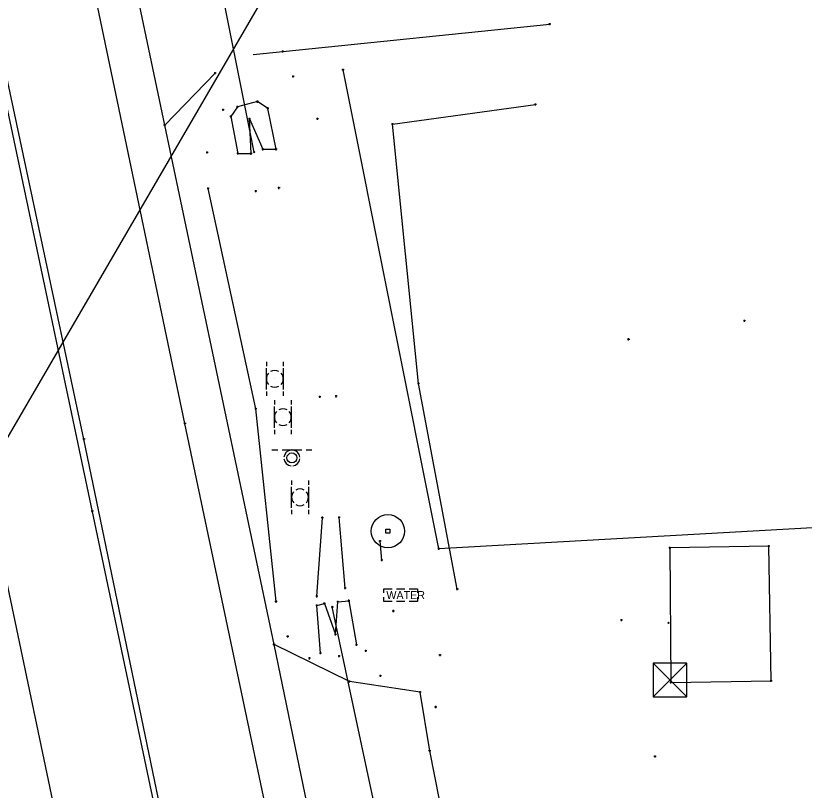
# Model space of a CAD drawing. Extents: x 1954856 to 2011933, y 399149 to 426294.
# Drawn here: x 2005465.1 to 2005558.7, y 405686.9 to 405778.8 of the extents above; entities that cross this region are included whole.
import ezdxf

# ---------------------------------------------------------------- set-up
doc = ezdxf.new("R2010")
doc.units = 0
for name, color, linetype in [('BankMent_ep', 7, 'Continuous'), ('BaselineSurvey', 7, 'Continuous'), ('Building_ep', 7, 'Continuous'), ('DelineatorPost_ep', 7, 'Continuous'), ('Driveway_ep', 7, 'Continuous'), ('ElecAer_ep', 7, 'Continuous'), ('EndTreatMES_ep', 7, 'Continuous'), ('FFElev_ep', 7, 'Continuous'), ('FlowLineInvert_ep', 7, 'Continuous'), ('MeterWater_ep', 7, 'Continuous'), ('MonumentPIP_ep', 7, 'Continuous'), ('MonumentPST_ep', 7, 'Continuous'), ('PavtAsphalt_ep', 7, 'Continuous'), ('PavtAsphaltCrown_ep', 7, 'Continuous'), ('PipeCulvert_ep', 7, 'Continuous'), ('PointLocator_ep', 7, 'Continuous'), ('ShldrPaved_ep', 7, 'Continuous'), ('SignSingle_ep', 7, 'Continuous'), ('TreeLineWoods_ep', 7, 'Continuous')]:
    doc.layers.add(name, color=color, linetype=linetype)

msp = doc.modelspace()

# ---------------------------------------------------------------- linework, layer by layer
at = {"layer": 'BankMent_ep'}
for p, q in [((2005509.866, 405765.963), (2005526.829, 405768.288)), ((2005512.931, 405735.184), (2005509.866, 405765.963)), ((2005493.618, 405732.173), (2005487.978, 405758.332)), ((2005517.542, 405710.799), (2005512.931, 405735.184)), ((2005496.025, 405709.31), (2005493.618, 405732.173)), ((2005500.874, 405709.942), (2005501.526, 405719.269)), ((2005504.222, 405710.912), (2005503.519, 405719.305)), ((2005508.586, 405714.238), (2005508.368, 405716.469))]:
    msp.add_line(p, q, dxfattribs=at)
at = {"layer": 'BaselineSurvey'}
msp.add_line((2006223.925, 402174.382), (2005094.479, 407516.047), dxfattribs=at)
msp.add_line((2006223.925, 402174.382), (2005094.479, 407516.047), dxfattribs=at)
at = {"layer": 'Building_ep'}
msp.add_lwpolyline([(2005542.763, 405715.684), (2005542.9, 405699.706), (2005554.797, 405699.906), (2005554.528, 405715.904)], close=True, dxfattribs=at)
at = {"layer": 'DelineatorPost_ep'}
for p, q in [((2005494.879, 405737.743), (2005494.879, 405737.243)), ((2005496.879, 405737.743), (2005496.879, 405737.243)), ((2005494.879, 405734.493), (2005494.879, 405736.993)), ((2005496.879, 405736.993), (2005496.879, 405734.493)), ((2005495.879, 405735.743), (2005495.879, 405735.743)), ((2005494.879, 405734.243), (2005494.879, 405733.743)), ((2005496.879, 405734.243), (2005496.879, 405733.743)), ((2005495.842, 405733.196), (2005495.842, 405732.696)), ((2005497.842, 405733.196), (2005497.842, 405732.696)), ((2005495.842, 405729.946), (2005495.842, 405732.446)), ((2005497.842, 405732.446), (2005497.842, 405729.946)), ((2005496.842, 405731.196), (2005496.842, 405731.196)), ((2005495.842, 405729.696), (2005495.842, 405729.196)), ((2005497.842, 405729.696), (2005497.842, 405729.196)), ((2005497.874, 405723.689), (2005497.874, 405723.189)), ((2005499.874, 405723.689), (2005499.874, 405723.189)), ((2005497.874, 405720.439), (2005497.874, 405722.939)), ((2005499.874, 405722.939), (2005499.874, 405720.439)), ((2005498.874, 405721.689), (2005498.874, 405721.689)), ((2005497.874, 405720.189), (2005497.874, 405719.689)), ((2005499.874, 405720.189), (2005499.874, 405719.689))]:
    msp.add_line(p, q, dxfattribs=at)
for centre, start, end in [((2005495.879, 405735.743), 60, 120), ((2005495.879, 405735.743), 138.59038, 221.40962), ((2005495.879, 405735.743), 318.59038, 41.40962), ((2005495.879, 405735.743), 240, 300), ((2005496.842, 405731.196), 60, 120), ((2005496.842, 405731.196), 138.59038, 221.40962), ((2005496.842, 405731.196), 318.59038, 41.40962), ((2005496.842, 405731.196), 240, 300), ((2005498.874, 405721.689), 60, 120), ((2005498.874, 405721.689), 138.59038, 221.40962), ((2005498.874, 405721.689), 318.59038, 41.40962), ((2005498.874, 405721.689), 240, 300)]:
    msp.add_arc(centre, 1, start, end, dxfattribs=at)
at = {"layer": 'Driveway_ep'}
for p, q in [((2005496.847, 405774.568), (2005528.511, 405777.824)), ((2005493.321, 405774.205), (2005496.847, 405774.568)), ((2005482.813, 405765.828), (2005488.806, 405772.014)), ((2005504.757, 405699.836), (2005495.79, 405704.209)), ((2005513.127, 405698.573), (2005504.757, 405699.836)), ((2005514.267, 405691.6), (2005513.127, 405698.573)), ((2005515.427, 405685.81), (2005514.267, 405691.6))]:
    msp.add_line(p, q, dxfattribs=at)
at = {"layer": 'ElecAer_ep'}
msp.add_lwpolyline([(2005445.498, 405696.718), (2005506.92, 405802.26), (2005520.719, 405804.021)], dxfattribs=at)
at = {"layer": 'EndTreatMES_ep'}
for p, q in [((2005500.857, 405708.859), (2005501.763, 405709.093)), ((2005501.305, 405703.21), (2005500.857, 405708.859)), ((2005501.763, 405709.093), (2005503.097, 405705.431)), ((2005503.097, 405705.431), (2005503.368, 405709.284)), ((2005503.368, 405709.284), (2005504.672, 405709.421)), ((2005504.672, 405709.421), (2005505.576, 405704.194))]:
    msp.add_line(p, q, dxfattribs=at)
msp.add_lwpolyline([(2005491.488, 405762.491), (2005493.061, 405762.464), (2005492.875, 405766.589), (2005494.468, 405762.975), (2005496.024, 405762.977), (2005495.065, 405767.832), (2005493.825, 405768.631), (2005491.469, 405768.025), (2005490.656, 405766.866)], close=True, dxfattribs=at)
at = {"layer": 'FFElev_ep'}
for p, q in [((2005542.707, 405706.701), (2005542.531, 405706.877)), ((2005542.707, 405706.877), (2005542.531, 405706.701)), ((2005542.619, 405706.789), (2005542.619, 405706.789))]:
    msp.add_line(p, q, dxfattribs=at)
at = {"layer": 'FlowLineInvert_ep'}
for p, q in [((2005493.514, 405762.557), (2005493.338, 405762.733)), ((2005493.514, 405762.733), (2005493.338, 405762.557)), ((2005493.426, 405762.645), (2005493.426, 405762.645)), ((2005502.789, 405708.591), (2005502.613, 405708.767)), ((2005502.789, 405708.767), (2005502.613, 405708.591)), ((2005502.701, 405708.679), (2005502.701, 405708.679))]:
    msp.add_line(p, q, dxfattribs=at)
at = {"layer": 'MeterWater_ep'}
msp.add_line((2005510.812, 405710.087), (2005510.812, 405710.087), dxfattribs=at)
for points in [[(2005508.812, 405710.337), (2005508.812, 405710.839), (2005509.812, 405710.839)], [(2005510.312, 405710.839), (2005511.312, 405710.839)], [(2005511.812, 405710.839), (2005512.812, 405710.839), (2005512.812, 405710.337)], [(2005509.812, 405709.335), (2005508.812, 405709.335), (2005508.812, 405709.837)], [(2005512.812, 405709.837), (2005512.812, 405709.335), (2005511.812, 405709.335)], [(2005511.312, 405709.335), (2005510.312, 405709.335)]]:
    msp.add_lwpolyline(points, dxfattribs=at)
at = {"layer": 'MonumentPIP_ep'}
msp.add_line((2005509.308, 405717.673), (2005509.308, 405717.673), dxfattribs=at)
msp.add_lwpolyline([(2005509.076, 405717.441), (2005509.076, 405717.905), (2005509.54, 405717.905), (2005509.54, 405717.441)], close=True, dxfattribs=at)
msp.add_circle((2005509.308, 405717.673), 1.977, dxfattribs=at)
at = {"layer": 'MonumentPST_ep'}
for p, q in [((2005540.783, 405702.02), (2005544.787, 405698.016)), ((2005540.783, 405698.016), (2005544.787, 405702.02)), ((2005542.785, 405700.018), (2005542.785, 405700.018))]:
    msp.add_line(p, q, dxfattribs=at)
msp.add_lwpolyline([(2005540.783, 405698.016), (2005544.787, 405698.016), (2005544.787, 405702.02), (2005540.783, 405702.02), (2005540.783, 405698.016)], dxfattribs=at)
at = {"layer": 'PavtAsphalt_ep'}
for points in [[(2005671.308, 404850.405), (2005650.509, 404948.216), (2005629.891, 405046.05), (2005609.273, 405143.996), (2005588.249, 405241.94), (2005567.845, 405339.002), (2005547.044, 405437.092), (2005526.499, 405535.125), (2005505.871, 405632.565), (2005485.219, 405730.457), (2005464.504, 405829.378), (2005444.003, 405926.254), (2005423.249, 406024.104)], [(2005647.527, 404845.36), (2005626.419, 404943.283), (2005605.825, 405041.291), (2005585.161, 405139.301), (2005564.569, 405237.066), (2005543.611, 405334.993), (2005527.25, 405416.168), (2005502.474, 405530.372), (2005481.578, 405628.348), (2005460.909, 405726.598), (2005440.426, 405824.017), (2005419.925, 405921.902), (2005399.287, 406019.762)]]:
    msp.add_lwpolyline(points, dxfattribs=at)
at = {"layer": 'PavtAsphaltCrown_ep'}
msp.add_lwpolyline([(2005659.531, 404847.945), (2005638.673, 404945.697), (2005617.909, 405043.694), (2005597.24, 405141.46), (2005576.514, 405239.298), (2005555.953, 405336.916), (2005535.174, 405434.816), (2005514.411, 405532.803), (2005493.563, 405630.595), (2005473.232, 405728.595), (2005452.357, 405826.425), (2005431.937, 405924.199), (2005411.143, 406022.056)], dxfattribs=at)
at = {"layer": 'PipeCulvert_ep'}
for points in [[(2005493.426, 405762.645), (2005485.553, 405802.005)], [(2005510.175, 405673.705), (2005502.701, 405708.679)]]:
    msp.add_lwpolyline(points, dxfattribs=at)
at = {"layer": 'PointLocator_ep'}
for p, q in [((2005528.511, 405777.699), (2005528.511, 405777.949)), ((2005528.636, 405777.824), (2005528.386, 405777.824)), ((2005528.511, 405777.824), (2005528.511, 405777.824)), ((2005496.972, 405774.568), (2005496.722, 405774.568)), ((2005496.847, 405774.443), (2005496.847, 405774.693)), ((2005496.847, 405774.568), (2005496.847, 405774.568)), ((2005504.105, 405772.392), (2005503.855, 405772.392)), ((2005503.98, 405772.267), (2005503.98, 405772.517)), ((2005503.98, 405772.392), (2005503.98, 405772.392)), ((2005488.931, 405772.014), (2005488.681, 405772.014)), ((2005488.806, 405771.889), (2005488.806, 405772.139)), ((2005488.806, 405772.014), (2005488.806, 405772.014)), ((2005498.189, 405771.621), (2005497.939, 405771.621)), ((2005498.064, 405771.496), (2005498.064, 405771.746)), ((2005498.064, 405771.621), (2005498.064, 405771.621)), ((2005493.95, 405768.631), (2005493.7, 405768.631)), ((2005493.825, 405768.506), (2005493.825, 405768.756)), ((2005493.825, 405768.631), (2005493.825, 405768.631)), ((2005489.869, 405767.67), (2005489.619, 405767.67)), ((2005489.744, 405767.545), (2005489.744, 405767.795)), ((2005489.744, 405767.67), (2005489.744, 405767.67)), ((2005491.594, 405768.025), (2005491.344, 405768.025)), ((2005491.469, 405767.9), (2005491.469, 405768.15)), ((2005491.469, 405768.025), (2005491.469, 405768.025)), ((2005495.19, 405767.832), (2005494.94, 405767.832)), ((2005495.065, 405767.707), (2005495.065, 405767.957)), ((2005495.065, 405767.832), (2005495.065, 405767.832)), ((2005526.954, 405768.288), (2005526.704, 405768.288)), ((2005526.829, 405768.163), (2005526.829, 405768.413)), ((2005526.829, 405768.288), (2005526.829, 405768.288)), ((2005490.781, 405766.866), (2005490.531, 405766.866)), ((2005490.656, 405766.741), (2005490.656, 405766.991)), ((2005490.656, 405766.866), (2005490.656, 405766.866)), ((2005492.875, 405766.464), (2005492.875, 405766.714)), ((2005500.953, 405766.459), (2005500.953, 405766.709)), ((2005482.938, 405765.828), (2005482.688, 405765.828)), ((2005482.813, 405765.703), (2005482.813, 405765.953)), ((2005482.813, 405765.828), (2005482.813, 405765.828)), ((2005493, 405766.589), (2005492.75, 405766.589)), ((2005492.875, 405766.589), (2005492.875, 405766.589)), ((2005501.078, 405766.584), (2005500.828, 405766.584)), ((2005500.953, 405766.584), (2005500.953, 405766.584)), ((2005509.991, 405765.963), (2005509.741, 405765.963)), ((2005509.866, 405765.838), (2005509.866, 405766.088)), ((2005509.866, 405765.963), (2005509.866, 405765.963)), ((2005494.593, 405762.975), (2005494.343, 405762.975)), ((2005494.468, 405762.85), (2005494.468, 405763.1)), ((2005494.468, 405762.975), (2005494.468, 405762.975)), ((2005496.149, 405762.977), (2005495.899, 405762.977)), ((2005496.024, 405762.852), (2005496.024, 405763.102)), ((2005496.024, 405762.977), (2005496.024, 405762.977)), ((2005487.98, 405762.59), (2005487.73, 405762.59)), ((2005487.855, 405762.465), (2005487.855, 405762.715)), ((2005487.855, 405762.59), (2005487.855, 405762.59)), ((2005491.613, 405762.491), (2005491.363, 405762.491)), ((2005491.488, 405762.366), (2005491.488, 405762.616)), ((2005491.488, 405762.491), (2005491.488, 405762.491)), ((2005493.186, 405762.464), (2005492.936, 405762.464)), ((2005493.061, 405762.339), (2005493.061, 405762.589)), ((2005493.061, 405762.464), (2005493.061, 405762.464)), ((2005488.103, 405758.332), (2005487.853, 405758.332)), ((2005487.978, 405758.207), (2005487.978, 405758.457)), ((2005487.978, 405758.332), (2005487.978, 405758.332)), ((2005496.501, 405758.391), (2005496.251, 405758.391)), ((2005496.376, 405758.266), (2005496.376, 405758.516)), ((2005496.376, 405758.391), (2005496.376, 405758.391)), ((2005493.751, 405758.002), (2005493.501, 405758.002)), ((2005493.626, 405757.877), (2005493.626, 405758.127)), ((2005493.626, 405758.002), (2005493.626, 405758.002)), ((2005551.752, 405742.638), (2005551.502, 405742.638)), ((2005551.627, 405742.513), (2005551.627, 405742.763)), ((2005551.627, 405742.638), (2005551.627, 405742.638)), ((2005538.005, 405740.429), (2005537.755, 405740.429)), ((2005537.88, 405740.304), (2005537.88, 405740.554)), ((2005537.88, 405740.429), (2005537.88, 405740.429)), ((2005513.056, 405735.184), (2005512.806, 405735.184)), ((2005512.931, 405735.059), (2005512.931, 405735.309)), ((2005512.931, 405735.184), (2005512.931, 405735.184)), ((2005501.359, 405733.603), (2005501.109, 405733.603)), ((2005501.234, 405733.478), (2005501.234, 405733.728)), ((2005501.234, 405733.603), (2005501.234, 405733.603)), ((2005503.286, 405733.672), (2005503.036, 405733.672)), ((2005503.161, 405733.547), (2005503.161, 405733.797)), ((2005503.161, 405733.672), (2005503.161, 405733.672)), ((2005493.743, 405732.173), (2005493.493, 405732.173)), ((2005493.618, 405732.048), (2005493.618, 405732.298)), ((2005493.618, 405732.173), (2005493.618, 405732.173)), ((2005485.344, 405730.457), (2005485.094, 405730.457)), ((2005485.219, 405730.332), (2005485.219, 405730.582)), ((2005485.219, 405730.457), (2005485.219, 405730.457)), ((2005473.357, 405728.595), (2005473.107, 405728.595)), ((2005473.232, 405728.47), (2005473.232, 405728.72)), ((2005473.232, 405728.595), (2005473.232, 405728.595)), ((2005474.348, 405720.041), (2005474.098, 405720.041)), ((2005474.223, 405719.916), (2005474.223, 405720.166)), ((2005474.223, 405720.041), (2005474.223, 405720.041)), ((2005501.651, 405719.269), (2005501.401, 405719.269)), ((2005501.526, 405719.144), (2005501.526, 405719.394)), ((2005501.526, 405719.269), (2005501.526, 405719.269)), ((2005503.644, 405719.305), (2005503.394, 405719.305)), ((2005503.519, 405719.18), (2005503.519, 405719.43)), ((2005503.519, 405719.305), (2005503.519, 405719.305)), ((2005508.493, 405716.469), (2005508.243, 405716.469)), ((2005508.368, 405716.344), (2005508.368, 405716.594)), ((2005508.368, 405716.469), (2005508.368, 405716.469)), ((2005515.466, 405715.591), (2005515.216, 405715.591)), ((2005515.341, 405715.466), (2005515.341, 405715.716)), ((2005515.341, 405715.591), (2005515.341, 405715.591)), ((2005542.888, 405715.684), (2005542.638, 405715.684)), ((2005542.763, 405715.559), (2005542.763, 405715.809)), ((2005542.763, 405715.684), (2005542.763, 405715.684)), ((2005554.653, 405715.904), (2005554.403, 405715.904)), ((2005554.528, 405715.779), (2005554.528, 405716.029)), ((2005554.528, 405715.904), (2005554.528, 405715.904)), ((2005508.711, 405714.238), (2005508.461, 405714.238)), ((2005508.586, 405714.113), (2005508.586, 405714.363)), ((2005508.586, 405714.238), (2005508.586, 405714.238)), ((2005504.347, 405710.912), (2005504.097, 405710.912)), ((2005504.222, 405710.787), (2005504.222, 405711.037)), ((2005504.222, 405710.912), (2005504.222, 405710.912)), ((2005517.667, 405710.799), (2005517.417, 405710.799)), ((2005517.542, 405710.674), (2005517.542, 405710.924)), ((2005517.542, 405710.799), (2005517.542, 405710.799)), ((2005500.999, 405709.942), (2005500.749, 405709.942)), ((2005500.874, 405709.817), (2005500.874, 405710.067)), ((2005500.874, 405709.942), (2005500.874, 405709.942)), ((2005504.672, 405709.296), (2005504.672, 405709.546)), ((2005496.15, 405709.31), (2005495.9, 405709.31)), ((2005496.025, 405709.185), (2005496.025, 405709.435)), ((2005496.025, 405709.31), (2005496.025, 405709.31)), ((2005500.982, 405708.859), (2005500.732, 405708.859)), ((2005500.857, 405708.734), (2005500.857, 405708.984)), ((2005500.857, 405708.859), (2005500.857, 405708.859)), ((2005501.888, 405709.093), (2005501.638, 405709.093)), ((2005501.763, 405708.968), (2005501.763, 405709.218)), ((2005501.763, 405709.093), (2005501.763, 405709.093)), ((2005503.493, 405709.284), (2005503.243, 405709.284)), ((2005503.368, 405709.159), (2005503.368, 405709.409)), ((2005503.368, 405709.284), (2005503.368, 405709.284)), ((2005504.797, 405709.421), (2005504.547, 405709.421)), ((2005504.672, 405709.421), (2005504.672, 405709.421)), ((2005510.08, 405708.198), (2005509.83, 405708.198)), ((2005509.955, 405708.073), (2005509.955, 405708.323)), ((2005509.955, 405708.198), (2005509.955, 405708.198)), ((2005537.152, 405707.115), (2005536.902, 405707.115)), ((2005537.027, 405706.99), (2005537.027, 405707.24)), ((2005537.027, 405707.115), (2005537.027, 405707.115)), ((2005497.534, 405705.182), (2005497.284, 405705.182)), ((2005497.409, 405705.057), (2005497.409, 405705.307)), ((2005497.409, 405705.182), (2005497.409, 405705.182)), ((2005503.222, 405705.431), (2005502.972, 405705.431)), ((2005503.097, 405705.306), (2005503.097, 405705.556)), ((2005503.097, 405705.431), (2005503.097, 405705.431)), ((2005495.915, 405704.209), (2005495.665, 405704.209)), ((2005495.79, 405704.084), (2005495.79, 405704.334)), ((2005495.79, 405704.209), (2005495.79, 405704.209)), ((2005505.701, 405704.194), (2005505.451, 405704.194)), ((2005505.576, 405704.069), (2005505.576, 405704.319)), ((2005505.576, 405704.194), (2005505.576, 405704.194)), ((2005501.43, 405703.21), (2005501.18, 405703.21)), ((2005501.305, 405703.085), (2005501.305, 405703.335)), ((2005501.305, 405703.21), (2005501.305, 405703.21)), ((2005503.518, 405702.716), (2005503.518, 405702.966)), ((2005506.8, 405703.485), (2005506.55, 405703.485)), ((2005506.675, 405703.36), (2005506.675, 405703.61)), ((2005506.675, 405703.485), (2005506.675, 405703.485)), ((2005515.494, 405702.833), (2005515.494, 405703.083)), ((2005500.123, 405702.586), (2005499.873, 405702.586)), ((2005499.998, 405702.461), (2005499.998, 405702.711)), ((2005499.998, 405702.586), (2005499.998, 405702.586)), ((2005503.643, 405702.841), (2005503.393, 405702.841)), ((2005503.518, 405702.841), (2005503.518, 405702.841)), ((2005515.619, 405702.958), (2005515.369, 405702.958)), ((2005515.494, 405702.958), (2005515.494, 405702.958)), ((2005508.558, 405700.5), (2005508.308, 405700.5)), ((2005508.433, 405700.375), (2005508.433, 405700.625)), ((2005508.433, 405700.5), (2005508.433, 405700.5)), ((2005504.882, 405699.836), (2005504.632, 405699.836)), ((2005504.757, 405699.711), (2005504.757, 405699.961)), ((2005504.757, 405699.836), (2005504.757, 405699.836)), ((2005543.025, 405699.706), (2005542.775, 405699.706)), ((2005542.9, 405699.581), (2005542.9, 405699.831)), ((2005542.9, 405699.706), (2005542.9, 405699.706)), ((2005554.922, 405699.906), (2005554.672, 405699.906)), ((2005554.797, 405699.781), (2005554.797, 405700.031)), ((2005554.797, 405699.906), (2005554.797, 405699.906)), ((2005513.252, 405698.573), (2005513.002, 405698.573)), ((2005513.127, 405698.448), (2005513.127, 405698.698)), ((2005513.127, 405698.573), (2005513.127, 405698.573)), ((2005515.103, 405696.811), (2005514.853, 405696.811)), ((2005514.978, 405696.686), (2005514.978, 405696.936)), ((2005514.978, 405696.811), (2005514.978, 405696.811)), ((2005514.392, 405691.6), (2005514.142, 405691.6)), ((2005514.267, 405691.475), (2005514.267, 405691.725)), ((2005514.267, 405691.6), (2005514.267, 405691.6)), ((2005541.138, 405690.935), (2005540.888, 405690.935)), ((2005541.013, 405690.81), (2005541.013, 405691.06)), ((2005541.013, 405690.935), (2005541.013, 405690.935))]:
    msp.add_line(p, q, dxfattribs=at)
at = {"layer": 'ShldrPaved_ep'}
msp.add_lwpolyline([(2005661.005, 404921.045), (2005655.381, 404949.379), (2005634.665, 405046.767), (2005613.982, 405144.942), (2005594.719, 405236.592), (2005590.086, 405258.656), (2005572.528, 405339.946), (2005551.671, 405437.939), (2005530.811, 405538.066), (2005522.224, 405579.314), (2005510.995, 405633.611), (2005501.961, 405674.366), (2005495.79, 405704.209), (2005482.813, 405765.828), (2005476.98, 405793.672), (2005469.078, 405830.21), (2005448.738, 405927.162), (2005427.696, 406024.966)], dxfattribs=at)
at = {"layer": 'SignSingle_ep'}
for p, q in [((2005495.536, 405727.312), (2005496.236, 405727.312)), ((2005496.736, 405727.312), (2005499.086, 405727.312)), ((2005499.586, 405727.312), (2005500.286, 405727.312)), ((2005497.911, 405726.362), (2005497.911, 405726.362))]:
    msp.add_line(p, q, dxfattribs=at)
msp.add_circle((2005497.911, 405726.362), 0.594, dxfattribs=at)
for start, end in [(96.04233, 173.95767), (6.04233, 83.95767), (186.04233, 263.95767), (276.04233, 353.95767)]:
    msp.add_arc((2005497.911, 405726.362), 0.95, start, end, dxfattribs=at)
at = {"layer": 'TreeLineWoods_ep'}
msp.add_lwpolyline([(2005584.366, 405719.462), (2005515.341, 405715.591), (2005503.98, 405772.392)], dxfattribs=at)

# ---------------------------------------------------------------- texts
at = {"layer": 'MeterWater_ep'}
msp.add_text('WATER', height=0.95, dxfattribs=at).set_placement((2005509.123, 405709.615))

doc.saveas('drawing.dxf')
